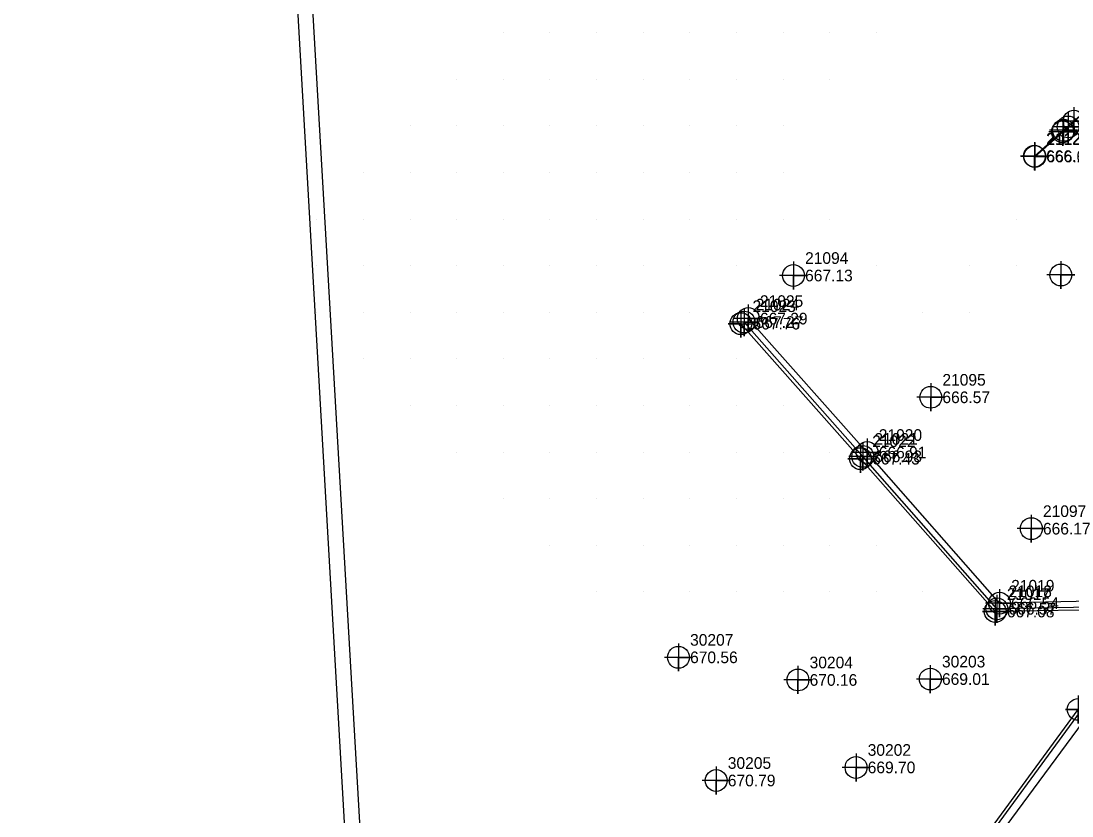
# Model space of a CAD drawing. Extents: x 1331606 to 1438728, y -485208 to 1373898.
# Drawn here: x 1378851.4 to 1379076.9, y 552686.9 to 552857.6 of the extents above; entities that cross this region are included whole.
import ezdxf

# ---------------------------------------------------------------- set-up
doc = ezdxf.new("R2010")
doc.units = 0
for name, color, linetype in [('Exist DTM Breakline', 7, 'Continuous'), ('Exist DTM Breakline Cogo Elevation', 7, 'Continuous'), ('Exist DTM Breakline Cogo Number', 7, 'Continuous'), ('Exist DTM Breakline Cogo Point CELL', 7, 'Continuous'), ('Exist DTM Drainline', 7, 'Continuous'), ('Exist DTM Drainline Cogo Elevation', 7, 'Continuous'), ('Exist DTM Drainline Cogo Number', 7, 'Continuous'), ('Exist DTM Drainline Cogo Point CELL', 7, 'Continuous'), ('Exist DTM QL2 LIDAR Elevation Point', 7, 'Continuous'), ('Exist DTM Regular Point CELL', 7, 'Continuous'), ('Exist DTM Regular Point Cogo Elevation', 7, 'Continuous'), ('Exist DTM Regular Point Cogo Number', 7, 'Continuous'), ('Exist Roads Curbs', 7, 'Continuous'), ('Exist Roads Curbs Cogo Elevation', 7, 'Continuous'), ('Exist Roads Curbs Cogo Number', 7, 'Continuous'), ('Exist Roads Curbs Cogo Point CELL', 7, 'Continuous'), ('Exist Roads EOP', 7, 'Continuous'), ('Exist Roads EOP Other', 7, 'Continuous'), ('Exist Roads EOP Other Cogo Elevation', 7, 'Continuous'), ('Exist Roads EOP Other Cogo Number', 7, 'Continuous'), ('Exist Roads EOP Other Cogo Point CELL', 7, 'Continuous')]:
    doc.layers.add(name, color=color, linetype=linetype)

msp = doc.modelspace()

# ---------------------------------------------------------------- linework, layer by layer
at = {"layer": 'Exist DTM Breakline'}
msp.add_lwpolyline([(1379068.9492, 552828.4974), (1379074.9311, 552833.7962), (1379076.0885, 552834.8421), (1379081.9254, 552840.0826000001), (1379084.3128, 552842.0559000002), (1379093.1148000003, 552849.6547)], dxfattribs=at)
at = {"layer": 'Exist DTM Breakline Cogo Point CELL'}
for points in [[(1379074.9311, 552836.7961999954), (1379074.9311, 552830.7961999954), (1379074.9311, 552833.7961999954), (1379077.9311, 552833.7961999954), (1379071.9311, 552833.7961999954)], [(1379076.0885, 552837.8420999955), (1379076.0885, 552831.8420999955), (1379076.0885, 552834.8420999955), (1379079.0885, 552834.8420999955), (1379073.0885, 552834.8420999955)], [(1379068.9492, 552831.4974000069), (1379068.9492, 552825.4974000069), (1379068.9492, 552828.4974000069), (1379071.9492, 552828.4974000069), (1379065.9492, 552828.4974000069)]]:
    msp.add_lwpolyline(points, dxfattribs=at)
for centre in [(1379076.0885, 552834.8420999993), (1379074.9311, 552833.7961999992), (1379068.9492, 552828.4974000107)]:
    msp.add_circle(centre, 2.344041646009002, dxfattribs=at)
at = {"layer": 'Exist DTM Drainline'}
for points in [[(1379089.5479, 552731.8869000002), (1379060.8152, 552731.4091), (1379032.0195, 552764.1240000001), (1379006.5465, 552792.9613)], [(1379024.4918, 552635.5159), (1379053.2758, 552674.5713), (1379080.1443, 552711.2440000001), (1379080.7651493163, 552712.0376760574)]]:
    msp.add_lwpolyline(points, dxfattribs=at)
at = {"layer": 'Exist DTM Drainline Cogo Point CELL'}
for points in [[(1379006.5465, 552795.9612999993), (1379006.5465, 552789.9612999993), (1379006.5465, 552792.9612999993), (1379009.5465, 552792.9612999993), (1379003.5465, 552792.9612999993)], [(1379032.0195, 552767.1239999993), (1379032.0195, 552761.1239999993), (1379032.0195, 552764.1239999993), (1379035.0195, 552764.1239999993), (1379029.0195, 552764.1239999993)], [(1379060.8152000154, 552734.4090999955), (1379060.8152000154, 552728.4090999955), (1379060.8152000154, 552731.4090999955), (1379063.8152000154, 552731.4090999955), (1379057.8152000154, 552731.4090999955)]]:
    msp.add_lwpolyline(points, dxfattribs=at)
for centre in [(1379006.5465, 552792.9612999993), (1379032.0195, 552764.1239999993), (1379060.8152000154, 552731.4090999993)]:
    msp.add_circle(centre, 2.344041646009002, dxfattribs=at)
at = {"layer": 'Exist DTM QL2 LIDAR Elevation Point'}
for p, q in [((1378954.9035921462, 552855.0555315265), (1378954.9035921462, 552855.0555315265)), ((1378964.905123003, 552855.0555315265), (1378964.905123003, 552855.0555315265)), ((1378974.90665386, 552855.0555315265), (1378974.90665386, 552855.0555315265)), ((1378984.9081847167, 552855.0555315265), (1378984.9081847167, 552855.0555315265)), ((1378994.9097155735, 552855.0555315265), (1378994.9097155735, 552855.0555315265)), ((1379004.9112464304, 552855.0555315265), (1379004.9112464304, 552855.0555315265)), ((1379014.9127772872, 552855.0555315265), (1379014.9127772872, 552855.0555315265)), ((1379024.914308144, 552855.0555315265), (1379024.914308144, 552855.0555315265)), ((1379034.915839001, 552855.0555315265), (1379034.915839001, 552855.0555315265)), ((1378944.9020612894, 552845.0540006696), (1378944.9020612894, 552845.0540006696)), ((1378954.9035921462, 552845.0540006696), (1378954.9035921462, 552845.0540006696)), ((1378964.905123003, 552845.0540006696), (1378964.905123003, 552845.0540006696)), ((1378974.90665386, 552845.0540006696), (1378974.90665386, 552845.0540006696)), ((1378984.9081847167, 552845.0540006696), (1378984.9081847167, 552845.0540006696)), ((1378994.9097155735, 552845.0540006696), (1378994.9097155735, 552845.0540006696)), ((1379004.9112464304, 552845.0540006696), (1379004.9112464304, 552845.0540006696)), ((1379014.9127772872, 552845.0540006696), (1379014.9127772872, 552845.0540006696)), ((1379024.914308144, 552845.0540006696), (1379024.914308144, 552845.0540006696)), ((1378934.9005304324, 552835.0524698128), (1378934.9005304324, 552835.0524698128)), ((1378944.9020612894, 552835.0524698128), (1378944.9020612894, 552835.0524698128)), ((1378954.9035921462, 552835.0524698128), (1378954.9035921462, 552835.0524698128)), ((1378964.905123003, 552835.0524698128), (1378964.905123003, 552835.0524698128)), ((1378974.90665386, 552835.0524698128), (1378974.90665386, 552835.0524698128)), ((1378984.9081847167, 552835.0524698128), (1378984.9081847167, 552835.0524698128)), ((1378994.9097155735, 552835.0524698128), (1378994.9097155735, 552835.0524698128)), ((1379004.9112464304, 552835.0524698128), (1379004.9112464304, 552835.0524698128)), ((1379014.9127772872, 552835.0524698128), (1379014.9127772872, 552835.0524698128)), ((1378924.8989995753, 552825.0509389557), (1378924.8989995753, 552825.0509389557)), ((1378934.9005304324, 552825.0509389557), (1378934.9005304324, 552825.0509389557)), ((1378944.9020612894, 552825.0509389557), (1378944.9020612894, 552825.0509389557)), ((1378954.9035921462, 552825.0509389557), (1378954.9035921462, 552825.0509389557)), ((1378964.905123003, 552825.0509389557), (1378964.905123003, 552825.0509389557)), ((1378974.90665386, 552825.0509389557), (1378974.90665386, 552825.0509389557)), ((1378984.9081847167, 552825.0509389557), (1378984.9081847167, 552825.0509389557)), ((1378994.9097155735, 552825.0509389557), (1378994.9097155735, 552825.0509389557)), ((1379004.9112464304, 552825.0509389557), (1379004.9112464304, 552825.0509389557)), ((1379014.9127772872, 552825.0509389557), (1379014.9127772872, 552825.0509389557)), ((1378914.8974687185, 552815.0494080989), (1378914.8974687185, 552815.0494080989)), ((1378924.8989995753, 552815.0494080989), (1378924.8989995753, 552815.0494080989)), ((1378934.9005304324, 552815.0494080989), (1378934.9005304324, 552815.0494080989)), ((1378944.9020612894, 552815.0494080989), (1378944.9020612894, 552815.0494080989)), ((1378954.9035921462, 552815.0494080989), (1378954.9035921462, 552815.0494080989)), ((1378964.905123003, 552815.0494080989), (1378964.905123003, 552815.0494080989)), ((1378974.90665386, 552815.0494080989), (1378974.90665386, 552815.0494080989)), ((1378984.9081847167, 552815.0494080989), (1378984.9081847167, 552815.0494080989)), ((1378994.9097155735, 552815.0494080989), (1378994.9097155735, 552815.0494080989)), ((1379004.9112464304, 552815.0494080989), (1379004.9112464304, 552815.0494080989)), ((1379014.9127772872, 552815.0494080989), (1379014.9127772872, 552815.0494080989)), ((1379024.914308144, 552815.0494080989), (1379024.914308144, 552815.0494080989)), ((1379064.9204315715, 552815.0494080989), (1379064.9204315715, 552815.0494080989)), ((1378914.8974687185, 552805.0478772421), (1378914.8974687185, 552805.0478772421)), ((1378924.8989995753, 552805.0478772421), (1378924.8989995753, 552805.0478772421)), ((1378934.9005304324, 552805.0478772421), (1378934.9005304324, 552805.0478772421)), ((1378944.9020612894, 552805.0478772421), (1378944.9020612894, 552805.0478772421)), ((1378954.9035921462, 552805.0478772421), (1378954.9035921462, 552805.0478772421)), ((1378964.905123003, 552805.0478772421), (1378964.905123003, 552805.0478772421)), ((1378974.90665386, 552805.0478772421), (1378974.90665386, 552805.0478772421)), ((1378984.9081847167, 552805.0478772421), (1378984.9081847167, 552805.0478772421)), ((1378994.9097155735, 552805.0478772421), (1378994.9097155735, 552805.0478772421)), ((1379004.9112464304, 552805.0478772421), (1379004.9112464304, 552805.0478772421)), ((1379024.914308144, 552805.0478772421), (1379024.914308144, 552805.0478772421)), ((1379034.915839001, 552805.0478772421), (1379034.915839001, 552805.0478772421)), ((1379054.9189007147, 552805.0478772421), (1379054.9189007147, 552805.0478772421)), ((1379064.9204315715, 552805.0478772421), (1379064.9204315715, 552805.0478772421)), ((1378914.8974687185, 552795.0463463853), (1378914.8974687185, 552795.0463463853)), ((1378924.8989995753, 552795.0463463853), (1378924.8989995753, 552795.0463463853)), ((1378934.9005304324, 552795.0463463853), (1378934.9005304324, 552795.0463463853)), ((1378944.9020612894, 552795.0463463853), (1378944.9020612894, 552795.0463463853)), ((1378954.9035921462, 552795.0463463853), (1378954.9035921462, 552795.0463463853)), ((1378964.905123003, 552795.0463463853), (1378964.905123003, 552795.0463463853)), ((1378974.90665386, 552795.0463463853), (1378974.90665386, 552795.0463463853)), ((1378984.9081847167, 552795.0463463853), (1378984.9081847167, 552795.0463463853)), ((1378994.9097155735, 552795.0463463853), (1378994.9097155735, 552795.0463463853)), ((1379044.917369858, 552795.0463463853), (1379044.917369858, 552795.0463463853)), ((1379054.9189007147, 552795.0463463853), (1379054.9189007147, 552795.0463463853)), ((1378924.8989995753, 552785.0448155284), (1378924.8989995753, 552785.0448155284)), ((1378934.9005304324, 552785.0448155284), (1378934.9005304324, 552785.0448155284)), ((1378944.9020612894, 552785.0448155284), (1378944.9020612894, 552785.0448155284)), ((1378954.9035921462, 552785.0448155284), (1378954.9035921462, 552785.0448155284)), ((1378964.905123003, 552785.0448155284), (1378964.905123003, 552785.0448155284)), ((1378974.90665386, 552785.0448155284), (1378974.90665386, 552785.0448155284)), ((1378984.9081847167, 552785.0448155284), (1378984.9081847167, 552785.0448155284)), ((1378994.9097155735, 552785.0448155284), (1378994.9097155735, 552785.0448155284)), ((1379004.9112464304, 552785.0448155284), (1379004.9112464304, 552785.0448155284)), ((1378934.9005304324, 552775.0432846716), (1378934.9005304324, 552775.0432846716)), ((1378944.9020612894, 552775.0432846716), (1378944.9020612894, 552775.0432846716)), ((1378954.9035921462, 552775.0432846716), (1378954.9035921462, 552775.0432846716)), ((1378964.905123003, 552775.0432846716), (1378964.905123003, 552775.0432846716)), ((1378974.90665386, 552775.0432846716), (1378974.90665386, 552775.0432846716)), ((1378984.9081847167, 552775.0432846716), (1378984.9081847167, 552775.0432846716)), ((1378994.9097155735, 552775.0432846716), (1378994.9097155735, 552775.0432846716)), ((1379004.9112464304, 552775.0432846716), (1379004.9112464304, 552775.0432846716)), ((1379014.9127772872, 552775.0432846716), (1379014.9127772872, 552775.0432846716)), ((1378944.9020612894, 552765.0417538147), (1378944.9020612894, 552765.0417538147)), ((1378954.9035921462, 552765.0417538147), (1378954.9035921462, 552765.0417538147)), ((1378964.905123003, 552765.0417538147), (1378964.905123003, 552765.0417538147)), ((1378974.90665386, 552765.0417538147), (1378974.90665386, 552765.0417538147)), ((1378984.9081847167, 552765.0417538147), (1378984.9081847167, 552765.0417538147)), ((1378994.9097155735, 552765.0417538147), (1378994.9097155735, 552765.0417538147)), ((1379004.9112464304, 552765.0417538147), (1379004.9112464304, 552765.0417538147)), ((1379014.9127772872, 552765.0417538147), (1379014.9127772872, 552765.0417538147)), ((1379024.914308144, 552765.0417538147), (1379024.914308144, 552765.0417538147)), ((1378954.9035921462, 552755.0402229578), (1378954.9035921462, 552755.0402229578)), ((1378964.905123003, 552755.0402229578), (1378964.905123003, 552755.0402229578)), ((1378974.90665386, 552755.0402229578), (1378974.90665386, 552755.0402229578)), ((1378984.9081847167, 552755.0402229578), (1378984.9081847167, 552755.0402229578)), ((1378994.9097155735, 552755.0402229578), (1378994.9097155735, 552755.0402229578)), ((1379004.9112464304, 552755.0402229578), (1379004.9112464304, 552755.0402229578)), ((1379014.9127772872, 552755.0402229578), (1379014.9127772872, 552755.0402229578)), ((1379024.914308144, 552755.0402229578), (1379024.914308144, 552755.0402229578)), ((1378964.905123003, 552745.038692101), (1378964.905123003, 552745.038692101)), ((1378974.90665386, 552745.038692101), (1378974.90665386, 552745.038692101)), ((1378984.9081847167, 552745.038692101), (1378984.9081847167, 552745.038692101)), ((1378994.9097155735, 552745.038692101), (1378994.9097155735, 552745.038692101)), ((1379004.9112464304, 552745.038692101), (1379004.9112464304, 552745.038692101)), ((1379014.9127772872, 552745.038692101), (1379014.9127772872, 552745.038692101)), ((1379024.914308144, 552745.038692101), (1379024.914308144, 552745.038692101)), ((1379034.915839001, 552745.038692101), (1379034.915839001, 552745.038692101)), ((1378974.90665386, 552735.0371612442), (1378974.90665386, 552735.0371612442)), ((1378984.9081847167, 552735.0371612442), (1378984.9081847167, 552735.0371612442)), ((1378994.9097155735, 552735.0371612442), (1378994.9097155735, 552735.0371612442)), ((1379004.9112464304, 552735.0371612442), (1379004.9112464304, 552735.0371612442)), ((1379014.9127772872, 552735.0371612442), (1379014.9127772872, 552735.0371612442)), ((1379024.914308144, 552735.0371612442), (1379024.914308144, 552735.0371612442)), ((1379034.915839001, 552735.0371612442), (1379034.915839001, 552735.0371612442)), ((1379044.917369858, 552735.0371612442), (1379044.917369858, 552735.0371612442)), ((1379074.9219624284, 552705.0325686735), (1379074.9219624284, 552705.0325686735))]:
    msp.add_line(p, q, dxfattribs=at)
at = {"layer": 'Exist DTM Regular Point CELL'}
for points in [[(1379017.146599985, 552805.9491999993), (1379017.146599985, 552799.9491999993), (1379017.146599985, 552802.9491999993), (1379020.146599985, 552802.9491999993), (1379014.146599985, 552802.9491999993)], [(1379074.5495, 552806.0641999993), (1379074.5495, 552800.0641999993), (1379074.5495, 552803.0641999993), (1379077.5495, 552803.0641999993), (1379071.5495, 552803.0641999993)], [(1379046.6159, 552779.8100999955), (1379046.6159, 552773.8100999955), (1379046.6159, 552776.8100999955), (1379049.6159, 552776.8100999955), (1379043.6159, 552776.8100999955)], [(1379068.1962999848, 552751.6090999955), (1379068.1962999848, 552745.6090999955), (1379068.1962999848, 552748.6090999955), (1379071.1962999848, 552748.6090999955), (1379065.1962999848, 552748.6090999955)], [(1378992.47, 552723.9828), (1378992.47, 552717.9828), (1378992.47, 552720.9828), (1378995.47, 552720.9828), (1378989.47, 552720.9828)], [(1379018.1215000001, 552719.1283), (1379018.1215000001, 552713.1283), (1379018.1215000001, 552716.1283), (1379021.1215000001, 552716.1283), (1379015.1215000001, 552716.1283)], [(1379046.5264, 552719.3191), (1379046.5264, 552713.3191), (1379046.5264, 552716.3191), (1379049.5264, 552716.3191), (1379043.5264, 552716.3191)], [(1379030.5854000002, 552700.3494), (1379030.5854000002, 552694.3494), (1379030.5854000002, 552697.3494), (1379033.5854000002, 552697.3494), (1379027.5854000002, 552697.3494)], [(1379000.5687000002, 552697.5459), (1379000.5687000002, 552691.5459), (1379000.5687000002, 552694.5459), (1379003.5687000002, 552694.5459), (1378997.5687000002, 552694.5459)]]:
    msp.add_lwpolyline(points, dxfattribs=at)
for centre in [(1379017.146599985, 552802.9491999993), (1379074.5495, 552803.0641999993), (1379046.6159, 552776.8100999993), (1379068.1962999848, 552748.6090999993), (1378992.47, 552720.9828), (1379018.1215000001, 552716.1283), (1379046.5264, 552716.3191), (1379030.5854000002, 552697.349400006), (1379000.5687000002, 552694.545900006)]:
    msp.add_circle(centre, 2.344041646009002, dxfattribs=at)
at = {"layer": 'Exist Roads Curbs'}
for points in [[(1379089.3415, 552731.2742), (1379087.5564, 552731.2638), (1379060.4554, 552730.8169), (1379031.5465, 552763.6274), (1379005.8678, 552792.6133)], [(1379023.9036, 552635.8740000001), (1379052.7896, 552675.0054), (1379078.2698, 552709.8079)]]:
    msp.add_lwpolyline(points, dxfattribs=at)
at = {"layer": 'Exist Roads Curbs Cogo Point CELL'}
for points in [[(1379005.8677999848, 552795.6132999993), (1379005.8677999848, 552789.6132999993), (1379005.8677999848, 552792.6132999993), (1379003.1377999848, 552792.6132999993), (1379008.8677999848, 552792.6132999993)], [(1379031.5465, 552766.6274000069), (1379031.5465, 552760.6274000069), (1379031.5465, 552763.6274000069), (1379028.8165, 552763.6274000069), (1379034.5465, 552763.6274000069)], [(1379060.4554, 552733.8169000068), (1379060.4554, 552727.8169000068), (1379060.4554, 552730.8169000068), (1379057.7254, 552730.8169000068), (1379063.4554, 552730.8169000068)], [(1379078.2697999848, 552712.8079000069), (1379078.2697999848, 552706.8079000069), (1379078.2697999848, 552709.8079000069), (1379075.5397999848, 552709.8079000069), (1379081.2697999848, 552709.8079000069)]]:
    msp.add_lwpolyline(points, dxfattribs=at)
for centre in [(1379005.8677999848, 552792.6132999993), (1379031.5465, 552763.6274000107), (1379060.4554, 552730.8169000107), (1379078.2697999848, 552709.8079000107)]:
    msp.add_circle(centre, 2.344041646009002, dxfattribs=at)
at = {"layer": 'Exist Roads EOP'}
msp.add_lwpolyline([(1379025.9588, 552634.5552), (1379054.7337, 552673.794), (1379081.6403000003, 552710.1902), (1379082.1494293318, 552711.0332302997)], dxfattribs=at)
at = {"layer": 'Exist Roads EOP Other'}
for points in [[(1379068.8679, 552828.5847), (1379075.1225, 552834.1245), (1379077.3343, 552836.0972), (1379081.3344, 552839.6336), (1379082.8678, 552840.9804), (1379092.8881, 552849.7216)], [(1379090.9762, 552733.267), (1379061.3715000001, 552732.6025), (1379032.9667, 552764.9581), (1379007.4603, 552793.7078)]]:
    msp.add_lwpolyline(points, dxfattribs=at)
msp.add_spline([(1378930.0704, 552542.9155), (1378932.5817, 552537.9158), (1378932.5817, 552537.9158), (1378929.449, 552534.7859), (1378926.8962, 552542.0254000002)], degree=3, dxfattribs=at)
at = {"layer": 'Exist Roads EOP Other Cogo Point CELL'}
for points in [[(1379077.3342999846, 552839.0971999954), (1379077.3342999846, 552833.0971999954), (1379077.3342999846, 552836.0971999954), (1379080.3342999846, 552836.0971999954), (1379074.3342999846, 552836.0971999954)], [(1379075.1225, 552837.1244999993), (1379075.1225, 552831.1244999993), (1379075.1225, 552834.1244999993), (1379078.1225, 552834.1244999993), (1379072.1225, 552834.1244999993)], [(1379068.867900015, 552831.5846999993), (1379068.867900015, 552825.5846999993), (1379068.867900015, 552828.5846999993), (1379071.867900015, 552828.5846999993), (1379065.867900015, 552828.5846999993)], [(1379007.4602999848, 552796.7077999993), (1379007.4602999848, 552790.7077999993), (1379007.4602999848, 552793.7077999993), (1379010.4602999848, 552793.7077999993), (1379004.4602999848, 552793.7077999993)], [(1379032.9667000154, 552767.9580999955), (1379032.9667000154, 552761.9580999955), (1379032.9667000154, 552764.9580999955), (1379035.9667000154, 552764.9580999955), (1379029.9667000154, 552764.9580999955)], [(1379061.3715000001, 552735.6024999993), (1379061.3715000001, 552729.6024999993), (1379061.3715000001, 552732.6024999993), (1379064.3715000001, 552732.6024999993), (1379058.3715000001, 552732.6024999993)]]:
    msp.add_lwpolyline(points, dxfattribs=at)
for centre in [(1379077.3342999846, 552836.0971999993), (1379075.1225, 552834.1244999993), (1379068.867900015, 552828.5846999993), (1379007.4602999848, 552793.7077999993), (1379032.9667000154, 552764.9580999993), (1379061.3715000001, 552732.6024999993)]:
    msp.add_circle(centre, 2.344041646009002, dxfattribs=at)

# ---------------------------------------------------------------- texts
at = {"layer": 'Exist DTM Breakline Cogo Elevation'}
msp.add_text('666.22', height=2.5, dxfattribs=at).set_placement((1379071.4492, 552827.2474))
at = {"layer": 'Exist DTM Breakline Cogo Number'}
msp.add_text('21125', height=2.5, dxfattribs=at).set_placement((1379071.4492, 552830.9974))
at = {"layer": 'Exist DTM Drainline Cogo Elevation'}
for s, p in [('667.27', (1379009.0465, 552791.7113)), ('666.93', (1379034.5195, 552762.8740000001)), ('666.57', (1379063.3152, 552730.1591))]:
    msp.add_text(s, height=2.5, dxfattribs=at).set_placement(p)
at = {"layer": 'Exist DTM Drainline Cogo Number'}
for s, p in [('21024', (1379009.0465, 552795.4613)), ('21021', (1379034.5195, 552766.6240000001)), ('21018', (1379063.3152, 552733.9091))]:
    msp.add_text(s, height=2.5, dxfattribs=at).set_placement(p)
at = {"layer": 'Exist DTM Regular Point Cogo Elevation'}
for s, p in [('667.13', (1379019.6466, 552801.6992)), ('666.57', (1379049.1159, 552775.5601)), ('666.17', (1379070.6963, 552747.3591)), ('670.56', (1378994.97, 552719.7328)), ('670.16', (1379020.6215000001, 552714.8783)), ('669.01', (1379049.0264, 552715.0691)), ('669.70', (1379033.0854000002, 552696.0994)), ('670.79', (1379003.0687000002, 552693.2959))]:
    msp.add_text(s, height=2.5, dxfattribs=at).set_placement(p)
at = {"layer": 'Exist DTM Regular Point Cogo Number'}
for s, p in [('21094', (1379019.6466, 552805.4492)), ('21095', (1379049.1159, 552779.3101)), ('21097', (1379070.6963, 552751.1091)), ('30207', (1378994.97, 552723.4828)), ('30204', (1379020.6215000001, 552718.6283)), ('30203', (1379049.0264, 552718.8191)), ('30202', (1379033.0854000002, 552699.8494)), ('30205', (1379003.0687000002, 552697.0459))]:
    msp.add_text(s, height=2.5, dxfattribs=at).set_placement(p)
at = {"layer": 'Exist Roads Curbs Cogo Elevation'}
for s, p in [('667.76', (1379008.3678, 552791.3633)), ('667.43', (1379034.0465, 552762.3774)), ('667.08', (1379062.9554, 552729.5669))]:
    msp.add_text(s, height=2.5, dxfattribs=at).set_placement(p)
at = {"layer": 'Exist Roads Curbs Cogo Number'}
for s, p in [('21023', (1379008.3678, 552795.1133)), ('21022', (1379034.0465, 552766.1274)), ('21017', (1379062.9554, 552733.3169))]:
    msp.add_text(s, height=2.5, dxfattribs=at).set_placement(p)
at = {"layer": 'Exist Roads EOP Other Cogo Elevation'}
for s, p in [('666.68', (1379071.3679, 552827.3347)), ('667.29', (1379009.9603, 552792.4578)), ('666.91', (1379035.4667, 552763.7081)), ('666.54', (1379063.8715000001, 552731.3525))]:
    msp.add_text(s, height=2.5, dxfattribs=at).set_placement(p)
at = {"layer": 'Exist Roads EOP Other Cogo Number'}
for s, p in [('21124', (1379071.3679, 552831.0847)), ('21025', (1379009.9603, 552796.2078)), ('21020', (1379035.4667, 552767.4581)), ('21019', (1379063.8715000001, 552735.1025))]:
    msp.add_text(s, height=2.5, dxfattribs=at).set_placement(p)

doc.saveas('drawing.dxf')
